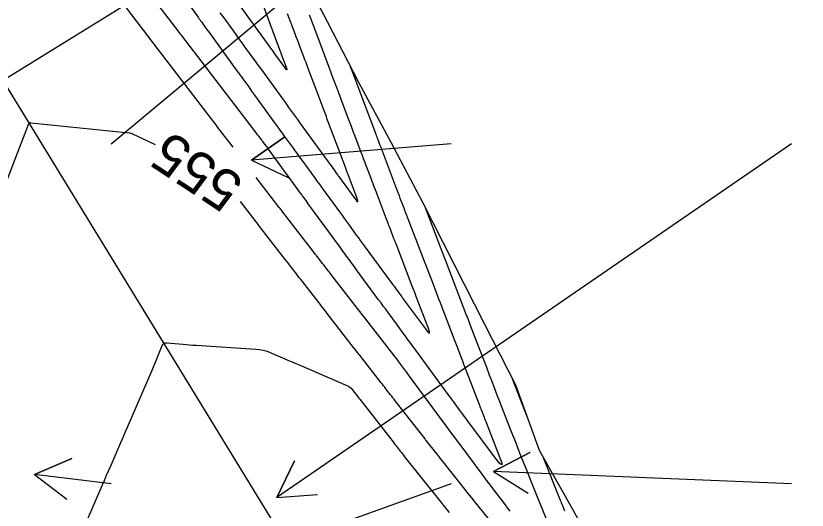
# Model space of a CAD drawing. Extents: x 954385 to 988206, y 1868364 to 1924553.
# Drawn here: x 957043.1 to 957159.4, y 1921015.1 to 1921087.7 of the extents above; entities that cross this region are included whole.
import ezdxf

# ---------------------------------------------------------------- set-up
doc = ezdxf.new("R2010")
doc.units = 0
for name, color, linetype in [('Default', 7, 'Continuous'), ('Ex_Contour Labels', 7, 'Continuous'), ('Ex_Major Contours', 7, 'Continuous'), ('Ex_Minor Contours', 7, 'Continuous'), ('Perimeter', 7, 'Continuous'), ('Slopes', 7, 'Continuous')]:
    doc.layers.add(name, color=color, linetype=linetype)

msp = doc.modelspace()

# ---------------------------------------------------------------- linework, layer by layer
at = {"layer": 'Default'}
msp.add_line((957221.14, 1920784.24), (956045.8, 1922705.18), dxfattribs=at)
at = {"layer": 'Ex_Major Contours'}
for points in [[(957079.17, 1921090.03), (957081.91, 1921082.77), (957081.99, 1921082.55), (957082.13, 1921082.16), (957082.15, 1921082.11), (957082.88, 1921080.17), (957082.97, 1921079.9), (957082.97, 1921079.8), (957082.88, 1921079.86), (957082.71, 1921080.07), (957081.22, 1921082.13), (957080.84, 1921082.66), (957080.75, 1921082.78), (957075.61, 1921089.87)], [(957063.66, 1921068.76), (957060.36, 1921070.32), (957060.22, 1921070.38), (957060.08, 1921070.42), (957059.94, 1921070.46), (957059.79, 1921070.48), (957045.36, 1921071.97), (957045.34, 1921071.97), (957045.32, 1921071.97), (957045.31, 1921071.97), (957045.29, 1921071.98), (957045.1, 1921072), (957045.09, 1921072), (957045.07, 1921071.99), (957045.07, 1921071.99), (957045.06, 1921071.97), (957044.99, 1921071.79), (957044.99, 1921071.78), (957044.98, 1921071.76), (957044.98, 1921071.75), (957044.97, 1921071.73), (957034.36, 1921044.36)], [(957115.8, 1921009.94), (957110.66, 1921016.24), (957110.14, 1921016.88), (957109.62, 1921017.53), (957109.1, 1921018.17), (957108.59, 1921018.82), (957105.94, 1921022.16), (957105.72, 1921022.44), (957105.5, 1921022.72), (957105.28, 1921023), (957105.06, 1921023.28), (957103.45, 1921025.3), (957103.41, 1921025.36), (957103.36, 1921025.42), (957103.31, 1921025.48), (957103.27, 1921025.54), (957098.9, 1921031.15), (957098.72, 1921031.37), (957098.55, 1921031.59), (957098.38, 1921031.81), (957098.21, 1921032.03), (957097.52, 1921032.92), (957097.35, 1921033.14), (957097.17, 1921033.36), (957097, 1921033.58), (957096.83, 1921033.8), (957093.97, 1921037.47), (957093.67, 1921037.85), (957093.37, 1921038.24), (957093.07, 1921038.62), (957092.78, 1921039), (957088.89, 1921043.99), (957088.54, 1921044.44), (957088.19, 1921044.88), (957087.85, 1921045.33), (957087.5, 1921045.78), (957085.25, 1921048.66), (957085.03, 1921048.95), (957084.8, 1921049.24), (957084.58, 1921049.52), (957084.36, 1921049.81), (957083.46, 1921050.97), (957083.24, 1921051.26), (957083.02, 1921051.55), (957082.79, 1921051.84), (957082.57, 1921052.12), (957078.86, 1921056.93), (957078.76, 1921057.06), (957078.65, 1921057.2), (957078.55, 1921057.33), (957078.45, 1921057.46), (957076.16, 1921060.46)], [(957116.01, 1921034.57), (957116.39, 1921033.59), (957116.44, 1921033.46), (957116.45, 1921033.43), (957116.46, 1921033.39), (957118.28, 1921028.75)], [(957120.52, 1921023.03), (957123.13, 1921016.54), (957123.21, 1921016.34), (957123.29, 1921016.14), (957123.37, 1921015.94), (957123.45, 1921015.75), (957123.77, 1921014.95)]]:
    msp.add_lwpolyline(points, dxfattribs=at)
at = {"layer": 'Ex_Minor Contours'}
for points in [[(957064.81, 1921094.62), (957069.92, 1921087.53), (957070.05, 1921087.35), (957070.17, 1921087.18), (957070.3, 1921087), (957070.42, 1921086.83), (957070.93, 1921086.13), (957071.18, 1921085.79), (957071.43, 1921085.44), (957075.63, 1921079.65), (957075.85, 1921079.36), (957076.06, 1921079.06), (957076.28, 1921078.76), (957076.49, 1921078.46), (957077.36, 1921077.27), (957077.79, 1921076.67), (957078.22, 1921076.08), (957081.31, 1921071.82), (957081.63, 1921071.38), (957081.95, 1921070.94), (957082.27, 1921070.49), (957082.59, 1921070.05), (957083.88, 1921068.28), (957084.2, 1921067.84), (957084.52, 1921067.39), (957084.84, 1921066.95), (957085.16, 1921066.51), (957087.01, 1921063.96), (957087.43, 1921063.39), (957087.84, 1921062.82), (957088.26, 1921062.25), (957088.67, 1921061.68), (957090.84, 1921058.71), (957091.13, 1921058.31), (957091.43, 1921057.91), (957091.72, 1921057.51), (957092.01, 1921057.11), (957093.17, 1921055.51), (957093.47, 1921055.11), (957093.76, 1921054.71), (957094.05, 1921054.32), (957094.34, 1921053.92), (957098.3, 1921048.54), (957098.44, 1921048.35), (957098.58, 1921048.16), (957098.72, 1921047.97), (957098.86, 1921047.77), (957099.42, 1921047.01), (957099.56, 1921046.82), (957099.7, 1921046.63), (957099.84, 1921046.44), (957099.98, 1921046.25), (957103.33, 1921041.7), (957103.73, 1921041.2), (957103.92, 1921041.07), (957103.92, 1921041.31), (957103.72, 1921041.91), (957102.02, 1921046.35), (957101.91, 1921046.63), (957101.81, 1921046.9), (957101.39, 1921048), (957099.01, 1921054.19), (957098.9, 1921054.49), (957098.78, 1921054.79), (957098.66, 1921055.1), (957098.55, 1921055.4), (957098.08, 1921056.61), (957097.97, 1921056.92), (957097.85, 1921057.22), (957097.74, 1921057.52), (957097.62, 1921057.83), (957095.99, 1921062.13), (957095.81, 1921062.59), (957095.64, 1921063.05), (957095.46, 1921063.51), (957095.29, 1921063.97), (957094.59, 1921065.81), (957094.41, 1921066.27), (957094.24, 1921066.73), (957094.06, 1921067.19), (957093.89, 1921067.65), (957092.95, 1921070.16), (957092.73, 1921070.73), (957092.52, 1921071.3), (957092.3, 1921071.87), (957092.09, 1921072.44), (957090.96, 1921075.45), (957090.8, 1921075.86), (957090.65, 1921076.26), (957090.5, 1921076.66), (957090.35, 1921077.07), (957089.74, 1921078.68), (957089.59, 1921079.08), (957089.44, 1921079.49), (957089.29, 1921079.89), (957089.13, 1921080.29), (957087.26, 1921085.28), (957087.16, 1921085.53), (957087.07, 1921085.79), (957086.97, 1921086.05), (957086.87, 1921086.3), (957086.49, 1921087.33), (957086.39, 1921087.59), (957086.29, 1921087.85)], [(957075.07, 1921068.42), (957073.18, 1921070.89), (957072.84, 1921071.33), (957072.51, 1921071.77), (957072.18, 1921072.2), (957071.84, 1921072.64), (957064.12, 1921082.72), (957063.93, 1921082.97), (957063.73, 1921083.23), (957063.53, 1921083.49), (957063.33, 1921083.75), (957062.54, 1921084.79), (957062.34, 1921085.05), (957062.15, 1921085.31), (957061.95, 1921085.57), (957061.75, 1921085.83), (957057.82, 1921091.01)], [(957092.28, 1921080.3), (957093.09, 1921078.16), (957093.2, 1921077.86), (957093.24, 1921077.75), (957096.02, 1921070.35), (957096.1, 1921070.15), (957096.18, 1921069.94), (957096.25, 1921069.74), (957096.33, 1921069.53), (957096.64, 1921068.71), (957096.72, 1921068.5), (957096.8, 1921068.3), (957096.87, 1921068.09), (957096.95, 1921067.89), (957099.04, 1921062.39), (957099.18, 1921062.03), (957099.31, 1921061.67), (957099.45, 1921061.31), (957099.59, 1921060.95), (957100.14, 1921059.51), (957100.27, 1921059.15), (957100.41, 1921058.79), (957100.55, 1921058.43), (957100.69, 1921058.06), (957102.11, 1921054.34), (957102.31, 1921053.83), (957102.5, 1921053.33), (957102.7, 1921052.82), (957102.89, 1921052.32), (957103.86, 1921049.79), (957104.44, 1921048.28), (957105.27, 1921046.12), (957105.47, 1921045.59), (957105.67, 1921045.06), (957105.88, 1921044.53), (957106.08, 1921044), (957107.41, 1921040.52), (957107.55, 1921040.16), (957107.69, 1921039.79), (957107.83, 1921039.43), (957107.97, 1921039.07), (957108.53, 1921037.62), (957108.67, 1921037.25), (957108.81, 1921036.89), (957108.94, 1921036.53), (957109.08, 1921036.17), (957111.16, 1921030.74), (957111.25, 1921030.52), (957111.33, 1921030.3), (957111.42, 1921030.08), (957111.51, 1921029.86), (957111.85, 1921028.97), (957111.94, 1921028.75), (957112.02, 1921028.53), (957112.11, 1921028.31), (957112.2, 1921028.09), (957114.28, 1921022.76), (957114.53, 1921022.02), (957114.53, 1921021.73), (957114.29, 1921021.89), (957113.79, 1921022.49), (957109.47, 1921028.29), (957109.25, 1921028.59), (957109.03, 1921028.89), (957108.81, 1921029.19), (957108.59, 1921029.49), (957107.71, 1921030.69), (957107.49, 1921030.99), (957107.27, 1921031.28), (957107.05, 1921031.58), (957106.83, 1921031.88), (957103.88, 1921035.9), (957103.48, 1921036.44), (957103.09, 1921036.98), (957102.69, 1921037.52), (957102.29, 1921038.06), (957100.61, 1921040.35), (957100.26, 1921040.82), (957099.91, 1921041.29), (957099.57, 1921041.76), (957099.22, 1921042.24), (957097.84, 1921044.12), (957097.49, 1921044.59), (957097.14, 1921045.06), (957096.8, 1921045.53), (957096.45, 1921046), (957093.21, 1921050.41), (957093.01, 1921050.68), (957092.81, 1921050.96), (957092.61, 1921051.23), (957092.41, 1921051.5), (957091.6, 1921052.6), (957091.4, 1921052.87), (957091.2, 1921053.15), (957091, 1921053.42), (957090.8, 1921053.7), (957086.12, 1921060.1), (957085.95, 1921060.33), (957085.78, 1921060.56), (957085.45, 1921061.02), (957085.37, 1921061.14), (957085.28, 1921061.25), (957085.2, 1921061.37), (957085.11, 1921061.48), (957080.29, 1921068.13), (957080.2, 1921068.26), (957080.11, 1921068.38), (957080.02, 1921068.5), (957079.92, 1921068.62), (957079.54, 1921069.13), (957079.45, 1921069.24), (957079.36, 1921069.36), (957079.28, 1921069.47), (957079.19, 1921069.58), (957078.84, 1921070.03), (957078.67, 1921070.26), (957078.5, 1921070.49), (957067.48, 1921084.88), (957067.36, 1921085.03), (957067.15, 1921085.31), (957067.13, 1921085.34), (957062.24, 1921091.77)], [(957073.14, 1921088.18), (957073.55, 1921087.61), (957075.36, 1921085.12), (957075.68, 1921084.67), (957076.01, 1921084.22), (957076.34, 1921083.77), (957076.66, 1921083.32), (957077.97, 1921081.52), (957078.29, 1921081.07), (957078.62, 1921080.62), (957078.95, 1921080.17), (957079.27, 1921079.72), (957082.37, 1921075.46), (957082.8, 1921074.87), (957083.22, 1921074.27), (957084.08, 1921073.09), (957084.51, 1921072.5), (957084.94, 1921071.91), (957089.57, 1921065.53), (957089.9, 1921065.07), (957090.23, 1921064.61), (957090.32, 1921064.5), (957090.4, 1921064.38), (957090.48, 1921064.27), (957090.57, 1921064.16), (957092.97, 1921060.86), (957093.26, 1921060.51), (957093.4, 1921060.41), (957093.4, 1921060.58), (957093.25, 1921061.02), (957092.03, 1921064.25), (957091.96, 1921064.43), (957091.89, 1921064.61), (957091.75, 1921064.98), (957091.71, 1921065.07), (957091.68, 1921065.17), (957091.64, 1921065.26), (957091.61, 1921065.35), (957089.05, 1921072.14), (957088.96, 1921072.4), (957088.86, 1921072.65), (957088.77, 1921072.91), (957088.67, 1921073.16), (957088.28, 1921074.18), (957088.19, 1921074.44), (957088.09, 1921074.7), (957088, 1921074.95), (957087.9, 1921075.21), (957086.09, 1921080.01), (957085.93, 1921080.43), (957085.78, 1921080.85), (957085.62, 1921081.27), (957085.46, 1921081.7), (957084.82, 1921083.38), (957084.66, 1921083.8), (957084.51, 1921084.22), (957084.35, 1921084.65), (957084.19, 1921085.07), (957083.08, 1921088)], [(957115.78, 1921014.92), (957115.43, 1921015.37), (957115.08, 1921015.83), (957113.3, 1921018.18), (957112.88, 1921018.73), (957112.47, 1921019.27), (957112.06, 1921019.82), (957111.65, 1921020.37), (957108.42, 1921024.7), (957108.23, 1921024.96), (957108.03, 1921025.23), (957107.84, 1921025.49), (957107.64, 1921025.75), (957106.86, 1921026.8), (957106.67, 1921027.06), (957106.47, 1921027.32), (957106.28, 1921027.59), (957106.08, 1921027.85), (957100.86, 1921034.95), (957100.73, 1921035.13), (957100.53, 1921035.41), (957100.46, 1921035.5), (957099.44, 1921036.89), (957099.26, 1921037.13), (957099.07, 1921037.38), (957098.89, 1921037.62), (957098.7, 1921037.86), (957089.58, 1921049.57), (957089.45, 1921049.74), (957089.31, 1921049.92), (957089.17, 1921050.09), (957089.04, 1921050.27), (957088.48, 1921050.99), (957088.35, 1921051.16), (957088.22, 1921051.32), (957088.09, 1921051.49), (957087.96, 1921051.66), (957087.44, 1921052.33), (957087.31, 1921052.5), (957087.18, 1921052.66), (957087.05, 1921052.83), (957086.92, 1921053), (957083.07, 1921057.98), (957082.97, 1921058.11), (957082.87, 1921058.24), (957082.77, 1921058.37), (957082.67, 1921058.5), (957082.27, 1921059.02), (957082.17, 1921059.15), (957082.06, 1921059.28), (957081.96, 1921059.41), (957081.86, 1921059.55), (957078.48, 1921063.97)], [(957103.18, 1921059.81), (957106.13, 1921052.12), (957106.22, 1921051.86), (957106.32, 1921051.61), (957106.71, 1921050.6), (957109.23, 1921044.02), (957109.33, 1921043.75), (957109.44, 1921043.49), (957109.54, 1921043.22), (957109.64, 1921042.96), (957110.05, 1921041.89), (957110.15, 1921041.63), (957110.25, 1921041.36), (957110.35, 1921041.09), (957110.46, 1921040.83), (957112.28, 1921036.07), (957112.44, 1921035.65), (957112.6, 1921035.23), (957112.76, 1921034.81), (957112.92, 1921034.39), (957113.57, 1921032.71), (957113.73, 1921032.28), (957113.89, 1921031.86), (957114.06, 1921031.44), (957114.22, 1921031.02), (957115.75, 1921027.1), (957115.94, 1921026.63), (957116.12, 1921026.16), (957116.3, 1921025.69), (957116.49, 1921025.22), (957117.22, 1921023.34), (957117.4, 1921022.87), (957117.59, 1921022.4), (957117.77, 1921021.93), (957117.96, 1921021.47), (957118.77, 1921019.47), (957118.96, 1921018.98), (957119.16, 1921018.49), (957119.36, 1921018), (957119.55, 1921017.51), (957121.15, 1921013.54)], [(957053.54, 1921013.33), (957055.85, 1921018.7), (957056.17, 1921019.45), (957056.49, 1921020.19), (957056.81, 1921020.93), (957057.13, 1921021.68), (957058.57, 1921024.99), (957058.82, 1921025.57), (957059.06, 1921026.14), (957059.31, 1921026.71), (957059.56, 1921027.28), (957063.18, 1921035.66), (957063.28, 1921035.9), (957063.38, 1921036.13), (957063.48, 1921036.37), (957063.58, 1921036.6), (957064.67, 1921039.27), (957064.77, 1921039.46), (957064.91, 1921039.58), (957065.08, 1921039.64), (957065.29, 1921039.65), (957067.71, 1921039.45), (957068.19, 1921039.41), (957068.67, 1921039.37), (957069.15, 1921039.34), (957069.63, 1921039.3), (957078.39, 1921038.74), (957078.96, 1921038.68), (957079.51, 1921038.57), (957080.06, 1921038.42), (957080.59, 1921038.21), (957082.69, 1921037.31), (957083.22, 1921037.09), (957083.74, 1921036.86), (957084.27, 1921036.64), (957084.79, 1921036.41), (957091.78, 1921033.41), (957092.01, 1921033.3), (957092.21, 1921033.16), (957092.4, 1921032.99), (957092.57, 1921032.8), (957093.45, 1921031.66), (957093.55, 1921031.55), (957093.73, 1921031.31), (957093.82, 1921031.19), (957098.38, 1921025.34), (957098.54, 1921025.14), (957098.7, 1921024.94), (957098.85, 1921024.74), (957099.01, 1921024.54), (957099.63, 1921023.73), (957099.79, 1921023.53), (957099.95, 1921023.33), (957100.11, 1921023.13), (957100.26, 1921022.93), (957105.62, 1921016.17), (957105.91, 1921015.81), (957106.21, 1921015.44), (957106.5, 1921015.07), (957106.8, 1921014.71)]]:
    msp.add_lwpolyline(points, dxfattribs=at)
at = {"layer": 'Perimeter'}
msp.add_lwpolyline([(957084.26, 1921095.8), (957088.9, 1921086.91), (957093.47, 1921077.98), (957098.24, 1921069.18), (957102.92, 1921060.32), (957107.46, 1921051.38), (957111.99, 1921042.42), (957116.56, 1921033.5), (957120.03, 1921023.9), (957124.96, 1921015.19), (957129.77, 1921006.41), (957135.24, 1920998.03), (957142.23, 1920990.59), (957147.77, 1920982.25), (957156.36, 1920975.79), (957167.75, 1920971.03)], dxfattribs=at)
at = {"layer": 'Slopes'}
for points in [[(957107.13, 1921118.93), (957024.32, 1921067.81), (957027.16, 1921073.09), (957024.32, 1921067.81), (957030.32, 1921067.99)], [(957057.13, 1921068.93), (957098.27, 1921103.28), (957096.2, 1921097.65), (957098.27, 1921103.28), (957092.36, 1921102.25)], [(957107.13, 1921068.93), (957077.76, 1921066.52), (957082.69, 1921069.93), (957077.76, 1921066.52), (957083.18, 1921063.95)], [(957157.13, 1921068.93), (957081.5, 1921016.92), (957084.08, 1921022.34), (957081.5, 1921016.92), (957087.48, 1921017.39)], [(957157.13, 1921018.93), (957113.34, 1921020.77), (957118.66, 1921023.55), (957113.34, 1921020.77), (957118.41, 1921017.55)], [(957057.13, 1921018.93), (957045.87, 1921020.31), (957051.39, 1921022.66), (957045.87, 1921020.31), (957050.66, 1921016.7)], [(957107.13, 1921018.93), (957054.45, 1921000.01), (957058.33, 1921004.59), (957054.45, 1921000.01), (957060.35, 1920998.94)]]:
    msp.add_lwpolyline(points, dxfattribs=at)

# ---------------------------------------------------------------- texts
at = {"layer": 'Ex_Contour Labels'}
msp.add_text('555', height=6, rotation=146.4893, dxfattribs=at).set_placement((957076.94, 1921063.58))

doc.saveas('drawing.dxf')
